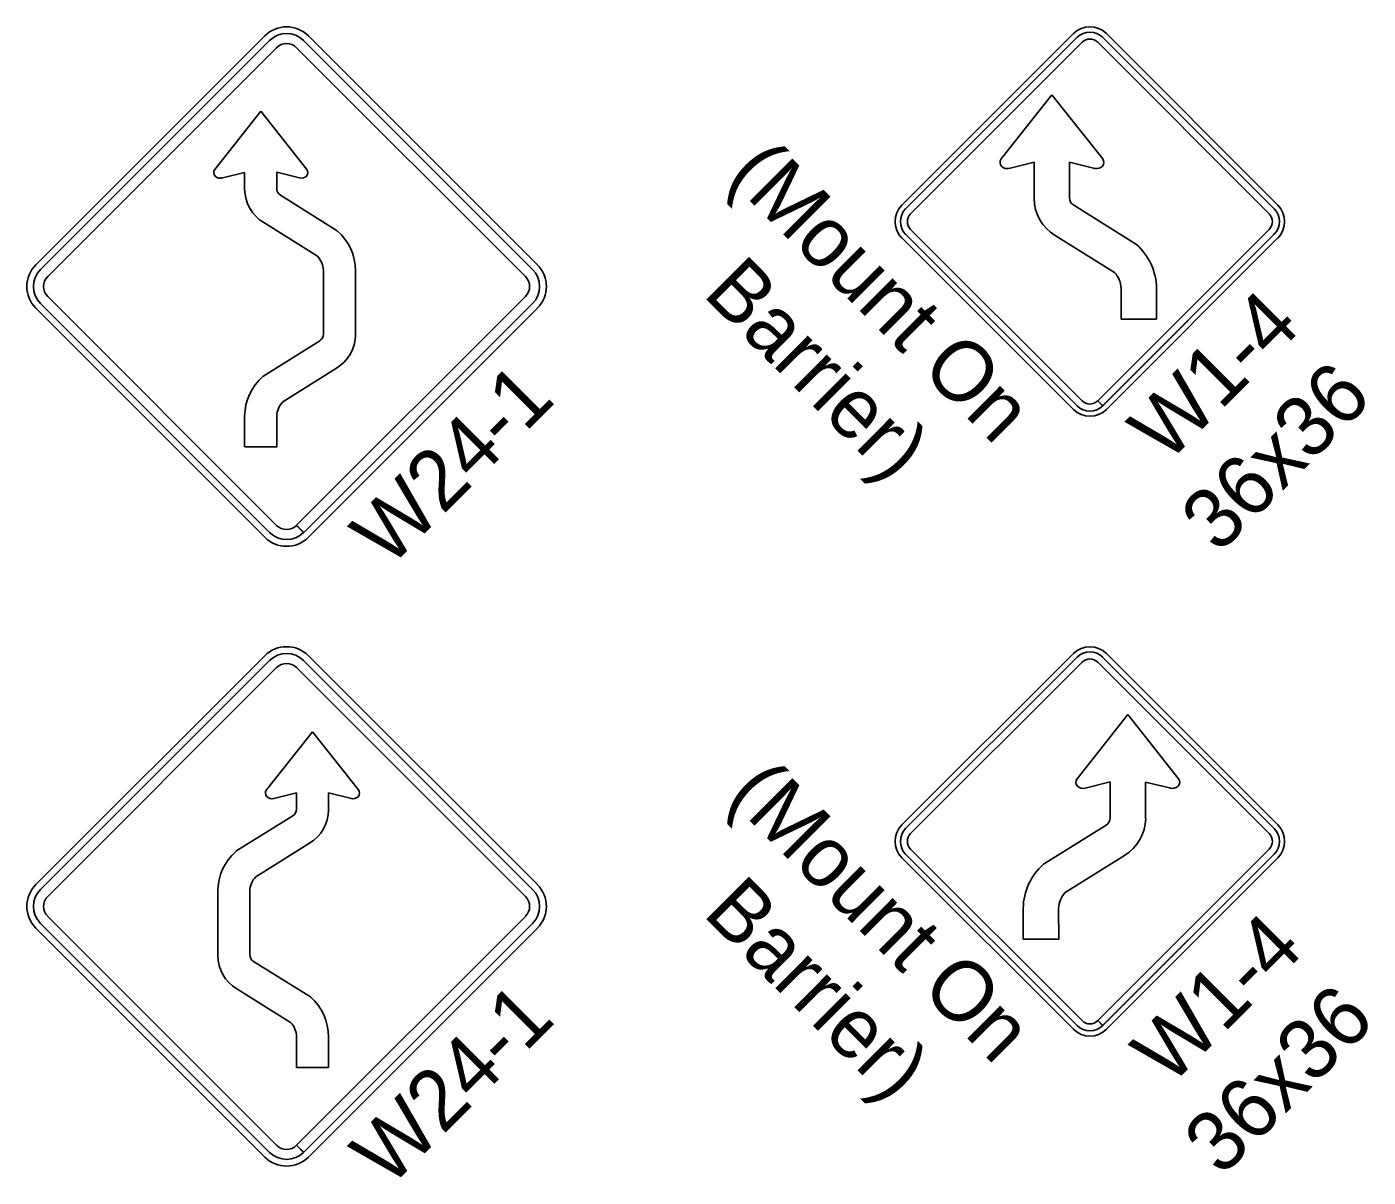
# Model space of a CAD drawing. Extents: x 1458 to 4498, y 17709 to 24109.
# Drawn here: x 2514 to 2848, y 23340.7 to 23627.2 of the extents above; entities that cross this region are included whole.
import ezdxf

# ---------------------------------------------------------------- set-up
doc = ezdxf.new("R2010")
doc.units = 0
doc.layers.add('P_TRAF_TCP_General', color=7, linetype='Continuous')

msp = doc.modelspace()

# ---------------------------------------------------------------- linework, layer by layer
at = {"layer": 'P_TRAF_TCP_General'}
for p, q in [((2573.24, 23624.96), (2516.24, 23567.95)), ((2641.1, 23567.95), (2584.09, 23624.96)), ((2774.57, 23625.51), (2731.88, 23582.82)), ((2825.46, 23582.82), (2782.77, 23625.51)), ((2574.43, 23623.78), (2517.42, 23566.77)), ((2574.43, 23623.78), (2517.42, 23566.77)), ((2519.19, 23565), (2576.19, 23622.01)), ((2519.19, 23565), (2576.19, 23622.01)), ((2581.14, 23622.01), (2638.15, 23565)), ((2581.14, 23622.01), (2638.15, 23565)), ((2639.91, 23566.77), (2582.91, 23623.78)), ((2639.91, 23566.77), (2582.91, 23623.78)), ((2775.49, 23624.59), (2732.8, 23581.9)), ((2775.49, 23624.59), (2732.8, 23581.9)), ((2734.03, 23580.66), (2776.72, 23623.35)), ((2780.61, 23623.35), (2823.3, 23580.66)), ((2824.54, 23581.9), (2781.85, 23624.59)), ((2824.54, 23581.9), (2781.85, 23624.59)), ((2756.6, 23594.31), (2769.23, 23610.29)), ((2769.23, 23610.29), (2781.87, 23594.31)), ((2572.25, 23606.19), (2560.8, 23591.7)), ((2572.25, 23606.19), (2560.8, 23591.7)), ((2583.7, 23591.7), (2572.25, 23606.19)), ((2583.7, 23591.7), (2572.25, 23606.19)), ((2583.7, 23591.7), (2583.7, 23591.7)), ((2764.79, 23593.49), (2758.83, 23592.03)), ((2764.79, 23584.43), (2764.79, 23593.49)), ((2779.87, 23591.95), (2773.61, 23593.51)), ((2773.61, 23593.51), (2773.61, 23584.65)), ((2562.83, 23589.64), (2568.22, 23590.97)), ((2562.83, 23589.64), (2568.22, 23590.97)), ((2568.22, 23590.97), (2568.22, 23586.8)), ((2568.22, 23590.97), (2568.22, 23586.8)), ((2576.22, 23586.96), (2576.22, 23590.98)), ((2576.22, 23590.98), (2581.89, 23589.57)), ((2576.22, 23586.96), (2576.22, 23590.98)), ((2576.22, 23590.98), (2581.89, 23589.57)), ((2591.29, 23576.42), (2577.15, 23585.26)), ((2591.29, 23576.42), (2577.15, 23585.26)), ((2774.64, 23582.76), (2790.25, 23573.01)), ((2572.97, 23578.44), (2586.37, 23570.07)), ((2572.97, 23578.44), (2586.37, 23570.07)), ((2731.88, 23574.62), (2774.57, 23531.93)), ((2732.8, 23575.54), (2775.49, 23532.84)), ((2732.8, 23575.54), (2775.49, 23532.84)), ((2776.72, 23534.08), (2734.03, 23576.77)), ((2784.81, 23566), (2770.03, 23575.24)), ((2823.3, 23576.77), (2780.62, 23534.09)), ((2781.85, 23532.84), (2824.54, 23575.54)), ((2781.86, 23532.86), (2824.54, 23575.54)), ((2782.77, 23531.93), (2825.46, 23574.62)), ((2587.85, 23566.5), (2587.85, 23550.51)), ((2595.84, 23550.51), (2595.84, 23566.5)), ((2786.43, 23554.41), (2786.45, 23562.06)), ((2795.27, 23562.06), (2795.26, 23554.39)), ((2517.42, 23558.29), (2574.43, 23501.28)), ((2517.42, 23558.29), (2574.43, 23501.28)), ((2576.19, 23503.05), (2519.19, 23560.06)), ((2638.15, 23560.06), (2581.16, 23503.07)), ((2638.15, 23560.06), (2581.16, 23503.07)), ((2582.93, 23501.3), (2639.91, 23558.29)), ((2582.93, 23501.3), (2639.91, 23558.29)), ((2516.24, 23557.11), (2573.24, 23500.1)), ((2584.09, 23500.1), (2641.1, 23557.11)), ((2795.26, 23554.39), (2786.43, 23554.41)), ((2586.92, 23549), (2572.77, 23540.16)), ((2577.7, 23533.81), (2591.1, 23542.18)), ((2781.85, 23532.84), (2780.61, 23534.08)), ((2780.62, 23534.09), (2781.86, 23532.86)), ((2568.22, 23530.24), (2568.22, 23522.58)), ((2576.22, 23522.58), (2576.22, 23530.24)), ((2568.25, 23522.58), (2576.25, 23522.58)), ((2582.91, 23501.28), (2581.14, 23503.05)), ((2582.91, 23501.28), (2581.14, 23503.05)), ((2581.16, 23503.07), (2582.93, 23501.3)), ((2581.16, 23503.07), (2582.93, 23501.3)), ((2774.57, 23471.15), (2731.88, 23428.46)), ((2825.46, 23428.46), (2782.77, 23471.15)), ((2573.24, 23470.61), (2516.24, 23413.6)), ((2574.43, 23469.42), (2517.42, 23412.42)), ((2574.43, 23469.42), (2517.42, 23412.42)), ((2639.91, 23412.42), (2582.91, 23469.42)), ((2639.91, 23412.42), (2582.91, 23469.42)), ((2641.1, 23413.6), (2584.09, 23470.61)), ((2775.49, 23470.24), (2732.8, 23427.54)), ((2775.49, 23470.24), (2732.8, 23427.54)), ((2734.03, 23426.31), (2776.72, 23469)), ((2780.61, 23469), (2823.3, 23426.31)), ((2824.54, 23427.54), (2781.85, 23470.24)), ((2824.54, 23427.54), (2781.85, 23470.24)), ((2519.19, 23410.65), (2576.19, 23467.65)), ((2519.19, 23410.65), (2576.19, 23467.65)), ((2581.14, 23467.65), (2638.15, 23410.65)), ((2581.14, 23467.65), (2638.15, 23410.65)), ((2788.1, 23455.94), (2775.47, 23439.95)), ((2800.74, 23439.95), (2788.1, 23455.94)), ((2573.66, 23437.17), (2585.11, 23451.65)), ((2573.66, 23437.17), (2585.11, 23451.65)), ((2585.11, 23451.65), (2596.55, 23437.17)), ((2585.11, 23451.65), (2596.55, 23437.17)), ((2777.47, 23437.6), (2783.72, 23439.16)), ((2783.72, 23439.16), (2783.72, 23430.29)), ((2792.55, 23439.14), (2798.5, 23437.67)), ((2792.55, 23430.07), (2792.55, 23439.14)), ((2573.66, 23437.17), (2573.66, 23437.17)), ((2581.14, 23436.45), (2575.47, 23435.04)), ((2581.14, 23436.45), (2575.47, 23435.04)), ((2581.14, 23432.43), (2581.14, 23436.45)), ((2581.14, 23432.43), (2581.14, 23436.45)), ((2594.53, 23435.1), (2589.14, 23436.43)), ((2589.14, 23436.43), (2589.14, 23432.26)), ((2594.53, 23435.1), (2589.14, 23436.43)), ((2589.14, 23436.43), (2589.14, 23432.26)), ((2566.07, 23421.89), (2580.21, 23430.73)), ((2566.07, 23421.89), (2580.21, 23430.73)), ((2782.7, 23428.41), (2767.09, 23418.65)), ((2584.39, 23423.91), (2570.99, 23415.53)), ((2584.39, 23423.91), (2570.99, 23415.53)), ((2732.8, 23421.18), (2775.49, 23378.49)), ((2732.8, 23421.18), (2775.49, 23378.49)), ((2776.72, 23379.73), (2734.03, 23422.42)), ((2823.3, 23422.42), (2780.62, 23379.74)), ((2781.85, 23378.49), (2824.54, 23421.18)), ((2781.86, 23378.5), (2824.54, 23421.18)), ((2731.88, 23420.26), (2774.57, 23377.57)), ((2772.52, 23411.64), (2787.31, 23420.88)), ((2782.77, 23377.57), (2825.46, 23420.26)), ((2561.51, 23395.97), (2561.51, 23411.97)), ((2569.51, 23411.97), (2569.51, 23395.97)), ((2762.07, 23407.71), (2762.08, 23400.04)), ((2770.9, 23400.05), (2770.89, 23407.71)), ((2576.19, 23348.7), (2519.19, 23405.7)), ((2638.15, 23405.7), (2581.16, 23348.71)), ((2638.15, 23405.7), (2581.16, 23348.71)), ((2516.24, 23402.75), (2573.24, 23345.75)), ((2517.42, 23403.93), (2574.43, 23346.93)), ((2582.93, 23346.95), (2639.91, 23403.93)), ((2582.93, 23346.95), (2639.91, 23403.93)), ((2584.09, 23345.75), (2641.1, 23402.75)), ((2762.08, 23400.04), (2770.9, 23400.05)), ((2570.44, 23394.47), (2584.58, 23385.63)), ((2579.66, 23379.28), (2566.26, 23387.65)), ((2781.85, 23378.49), (2780.61, 23379.73)), ((2780.62, 23379.74), (2781.86, 23378.5)), ((2581.14, 23368.05), (2581.14, 23375.71)), ((2589.14, 23375.71), (2589.14, 23368.05)), ((2589.11, 23368.05), (2581.11, 23368.05)), ((2582.91, 23346.93), (2581.14, 23348.7)), ((2582.91, 23346.93), (2581.14, 23348.7)), ((2581.16, 23348.71), (2582.93, 23346.95)), ((2581.16, 23348.71), (2582.93, 23346.95))]:
    msp.add_line(p, q, dxfattribs=at)
for centre, radius, start, end in [((2578.67, 23619.54), 7.67, 45, 135), ((2578.67, 23619.54), 6, 45, 135), ((2578.67, 23619.54), 6, 45, 135), ((2778.67, 23621.41), 5.8, 45, 135), ((2778.67, 23621.41), 4.5, 45, 135), ((2778.67, 23621.41), 4.5, 45, 135), ((2578.67, 23619.54), 3.5, 45, 135), ((2578.67, 23619.54), 3.5, 45, 135), ((2778.67, 23621.41), 2.75, 45, 135), ((2578.12, 23586.9), 9.9, 180.5603, 238.6466), ((2578.12, 23586.9), 9.9, 180.5603, 238.6466), ((2578.12, 23586.9), 1.9, 177.9228, 239.2343), ((2578.12, 23586.9), 1.9, 177.9228, 239.2343), ((2775.71, 23584.57), 2.1, 177.9228, 239.2343), ((2735.98, 23578.72), 5.8, 135, 225), ((2735.98, 23578.72), 4.5, 135, 225), ((2735.98, 23578.72), 4.5, 135, 225), ((2775.71, 23584.57), 10.93, 180.7484, 238.6466), ((2821.36, 23578.72), 4.5, 315, 45), ((2821.36, 23578.72), 4.5, 315, 45), ((2821.36, 23578.72), 5.8, 315, 45), ((2735.98, 23578.72), 2.75, 135, 225), ((2821.36, 23578.72), 2.75, 315, 45), ((2582.39, 23566.33), 13.46, 0.7428, 48.576), ((2582.39, 23566.33), 13.46, 0.7428, 48.576), ((2780.42, 23561.87), 14.85, 0.7428, 48.576), ((2521.66, 23562.53), 7.67, 135, 225), ((2582.47, 23566.36), 5.37, 1.5014, 43.5888), ((2582.47, 23566.36), 5.37, 1.5014, 43.5888), ((2635.67, 23562.53), 7.67, 315, 45), ((2521.66, 23562.53), 6, 135, 225), ((2521.66, 23562.53), 6, 135, 225), ((2521.66, 23562.53), 3.5, 135, 225), ((2521.66, 23562.53), 3.5, 135, 225), ((2635.67, 23562.53), 3.5, 315, 45), ((2635.67, 23562.53), 3.5, 315, 45), ((2635.67, 23562.53), 6, 315, 45), ((2635.67, 23562.53), 6, 315, 45), ((2780.52, 23561.91), 5.93, 1.5014, 43.5888), ((2585.94, 23550.64), 1.9, 300.7657, 2.0772), ((2585.94, 23550.64), 9.9, 301.3534, 359.2516), ((2581.68, 23530.07), 13.46, 131.424, 179.2572), ((2581.59, 23530.1), 5.37, 136.4112, 178.4986), ((2778.67, 23536.03), 5.8, 225, 315), ((2778.67, 23536.03), 4.5, 225, 315), ((2778.67, 23536.03), 4.5, 225, 315), ((2778.67, 23536.03), 2.75, 225, 315), ((2578.67, 23505.52), 6, 225, 315), ((2578.67, 23505.52), 6, 225, 315), ((2578.67, 23505.52), 3.5, 225, 315), ((2578.67, 23505.52), 3.5, 225, 315), ((2578.67, 23505.52), 7.67, 225, 315), ((2578.67, 23465.18), 7.67, 45, 135), ((2578.67, 23465.18), 6, 45, 135), ((2578.67, 23465.18), 6, 45, 135), ((2778.67, 23467.05), 5.8, 45, 135), ((2778.67, 23467.05), 4.5, 45, 135), ((2778.67, 23467.05), 4.5, 45, 135), ((2578.67, 23465.18), 3.5, 45, 135), ((2578.67, 23465.18), 3.5, 45, 135), ((2778.67, 23467.05), 2.75, 45, 135), ((2579.24, 23432.36), 1.9, 300.7657, 2.0772), ((2579.24, 23432.36), 1.9, 300.7657, 2.0772), ((2579.24, 23432.36), 9.9, 301.3534, 359.4397), ((2579.24, 23432.36), 9.9, 301.3534, 359.4397), ((2735.98, 23424.36), 5.8, 135, 225), ((2781.63, 23430.21), 2.1, 300.7657, 2.0772), ((2781.63, 23430.21), 10.93, 301.3534, 359.2516), ((2821.36, 23424.36), 5.8, 315, 45), ((2735.98, 23424.36), 4.5, 135, 225), ((2735.98, 23424.36), 4.5, 135, 225), ((2735.98, 23424.36), 2.75, 135, 225), ((2821.36, 23424.36), 2.75, 315, 45), ((2821.36, 23424.36), 4.5, 315, 45), ((2821.36, 23424.36), 4.5, 315, 45), ((2574.97, 23411.79), 13.46, 131.424, 179.2572), ((2574.97, 23411.79), 13.46, 131.424, 179.2572), ((2776.92, 23407.52), 14.85, 131.424, 179.2572), ((2574.88, 23411.83), 5.37, 136.4112, 178.4986), ((2574.88, 23411.83), 5.37, 136.4112, 178.4986), ((2521.66, 23408.18), 7.67, 135, 225), ((2521.66, 23408.18), 6, 135, 225), ((2521.66, 23408.18), 6, 135, 225), ((2635.67, 23408.18), 6, 315, 45), ((2635.67, 23408.18), 6, 315, 45), ((2635.67, 23408.18), 7.67, 315, 45), ((2776.82, 23407.55), 5.93, 136.4112, 178.4986), ((2521.66, 23408.18), 3.5, 135, 225), ((2521.66, 23408.18), 3.5, 135, 225), ((2635.67, 23408.18), 3.5, 315, 45), ((2635.67, 23408.18), 3.5, 315, 45), ((2571.41, 23396.1), 9.9, 180.7484, 238.6466), ((2571.41, 23396.1), 1.9, 177.9228, 239.2343), ((2575.68, 23375.54), 13.46, 0.7428, 48.576), ((2575.77, 23375.57), 5.37, 1.5014, 43.5888), ((2778.67, 23381.67), 5.8, 225, 315), ((2778.67, 23381.67), 4.5, 225, 315), ((2778.67, 23381.67), 4.5, 225, 315), ((2778.67, 23381.67), 2.75, 225, 315), ((2578.67, 23351.17), 3.5, 225, 315), ((2578.67, 23351.17), 3.5, 225, 315), ((2578.67, 23351.17), 7.67, 225, 315), ((2578.67, 23351.17), 6, 225, 315), ((2578.67, 23351.17), 6, 225, 315)]:
    msp.add_arc(centre, radius, start, end, dxfattribs=at)
for centre, major_axis, start_param, end_param in [((2562.16, 23590.92), (1.63, 0), 2.546183, 5.133903), ((2562.16, 23590.92), (1.63, 0), 2.546183, 5.133903), ((2582.35, 23590.92), (1.63, 0), 4.429962, 6.878595), ((2582.35, 23590.92), (1.63, 0), 4.429962, 6.878595), ((2758.09, 23593.44), (1.8, 0), 2.546183, 5.133903), ((2780.37, 23593.44), (1.8, 0), 4.429962, 6.878595), ((2776.96, 23439.08), (-1.8, 0), 5.687775, 8.136408), ((2799.24, 23439.08), (-1.8, 0), 1.149282, 3.737003), ((2575.01, 23436.38), (-1.63, 0), 5.687775, 8.136408), ((2575.01, 23436.38), (-1.63, 0), 5.687775, 8.136408), ((2595.2, 23436.38), (-1.63, 0), 1.149282, 3.737003), ((2595.2, 23436.38), (-1.63, 0), 1.149282, 3.737003)]:
    msp.add_ellipse(centre, major_axis=major_axis, ratio=0.857143, start_param=start_param, end_param=end_param, dxfattribs=at)

# ---------------------------------------------------------------- texts
for s, rotation, p in [('(Mount On', 315, (2688.11, 23589.71)), ('Barrier)', 315, (2682, 23560.49)), ('W1-4', 45, (2797.82, 23518.18)), ('W24-1', 45, (2604.18, 23492.16)), ('36x36', 45, (2810.74, 23495.76)), ('(Mount On', 315, (2688.11, 23435.36)), ('Barrier)', 315, (2682, 23406.13)), ('W1-4', 45, (2798.56, 23363.09)), ('36x36', 45, (2811.48, 23340.66)), ('W24-1', 45, (2604.18, 23337.81))]:
    msp.add_text(s, height=14.994, rotation=rotation, dxfattribs=at).set_placement(p)

doc.saveas('drawing.dxf')
